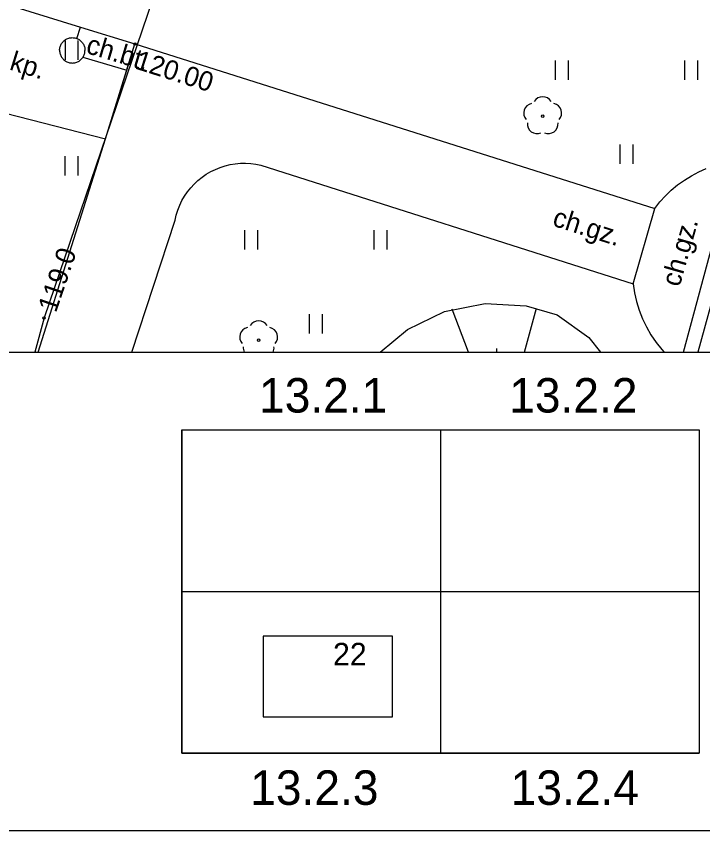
# Model space of a CAD drawing. Extents: x 6432121 to 6432331, y 5662538 to 5662686.
# Drawn here: x 6432202.58 to 6432229.11, y 5662537.55 to 5662569.04 of the extents above; entities that cross this region are included whole.
import ezdxf

# ---------------------------------------------------------------- set-up
doc = ezdxf.new("R2010")
doc.units = 0
for name, color, linetype in [('Warstwa 10', 7, 'Continuous'), ('Warstwa 11', 7, 'Continuous'), ('Warstwa 12', 7, 'Continuous'), ('Warstwa 14', 7, 'Continuous'), ('Warstwa 21', 7, 'Continuous'), ('Warstwa 25', 7, 'Continuous'), ('Warstwa 5', 7, 'Continuous'), ('Warstwa 63', 7, 'Continuous'), ('Warstwa 9', 7, 'Continuous')]:
    doc.layers.add(name, color=color, linetype=linetype)

msp = doc.modelspace()

# ---------------------------------------------------------------- linework, layer by layer
at = {"layer": 'Warstwa 10'}
for p, q in [((6432219.138, 5662557.621), (6432220.701, 5662557.93)), ((6432220.062, 5662556.053), (6432219.432, 5662557.711)), ((6432220.701, 5662557.93), (6432222.291, 5662557.843)), ((6432222.221, 5662556.053), (6432222.684, 5662557.758)), ((6432222.291, 5662557.843), (6432223.49, 5662557.5)), ((6432217.701, 5662556.933), (6432219.138, 5662557.621)), ((6432223.49, 5662557.5), (6432224.707, 5662556.621)), ((6432216.651, 5662556.053), (6432217.701, 5662556.933)), ((6432224.707, 5662556.621), (6432225.166, 5662556.053)), ((6432221.158, 5662556.053), (6432221.151, 5662556.197))]:
    msp.add_line(p, q, dxfattribs=at)
at = {"layer": 'Warstwa 11'}
for centre in [(6432222.929, 5662565.181), (6432211.95, 5662556.52)]:
    msp.add_circle(centre, 0.05, dxfattribs=at)
for centre, start, end in [((6432222.929, 5662565.556), 30.1471, 149.8529), ((6432222.572, 5662565.297), 102.1471, 221.8529), ((6432223.286, 5662565.297), 318.1471, 77.8529), ((6432222.709, 5662564.878), 174.1471, 293.8529), ((6432223.149, 5662564.878), 246.1471, 5.8529), ((6432211.95, 5662556.895), 30.1471, 149.8529), ((6432211.593, 5662556.636), 102.1471, 221.8529), ((6432212.307, 5662556.636), 318.1471, 77.8529), ((6432211.73, 5662556.217), 174.1471, 205.8431), ((6432212.17, 5662556.217), 334.1569, 5.8529)]:
    msp.add_arc(centre, 0.375, start, end, dxfattribs=at)
at = {"layer": 'Warstwa 12'}
for points in [[(6432127.185, 5662618.897), (6432135.629, 5662615.848), (6432142.79, 5662613.281), (6432154.997, 5662608.849), (6432160.46, 5662606.879), (6432165.736, 5662604.745), (6432167.852, 5662603.89), (6432175.869, 5662600.716), (6432188.607, 5662595.673), (6432197.141, 5662592.258), (6432208.285, 5662587.853), (6432217.328, 5662584.25), (6432226.269, 5662580.703), (6432229.116, 5662579.575), (6432234.631, 5662577.404), (6432234.076, 5662575.247), (6432232.817, 5662570.334), (6432230.472, 5662561.671), (6432228.926, 5662556.053)], [(6432228.367, 5662556.053), (6432231.658, 5662568.249), (6432233.96, 5662576.659), (6432221.597, 5662581.652), (6432210.31, 5662586.256), (6432196.752, 5662591.605), (6432184.96, 5662596.314), (6432169.081, 5662602.651), (6432160.264, 5662606.196), (6432148.936, 5662610.33), (6432147.827, 5662610.792), (6432135.842, 5662615.166), (6432127.959, 5662618.065)], [(6432211.625, 5662582.375), (6432211.84, 5662582.28), (6432211.83, 5662581.38), (6432203.66, 5662557.38), (6432203.3, 5662556.053)]]:
    msp.add_lwpolyline(points, dxfattribs=at)
at = {"layer": 'Warstwa 14'}
msp.add_circle((6432203.66, 5662557.38), 0.045, dxfattribs=at)
at = {"layer": 'Warstwa 21'}
for p, q in [((6432219.138, 5662557.621), (6432220.701, 5662557.93)), ((6432220.701, 5662557.93), (6432222.291, 5662557.843)), ((6432222.291, 5662557.843), (6432223.49, 5662557.5)), ((6432217.701, 5662556.933), (6432219.138, 5662557.621)), ((6432223.49, 5662557.5), (6432224.707, 5662556.621)), ((6432216.651, 5662556.053), (6432217.701, 5662556.933)), ((6432224.707, 5662556.621), (6432225.166, 5662556.053))]:
    msp.add_line(p, q, dxfattribs=at)
at = {"layer": 'Warstwa 25'}
msp.add_circle((6432207.17, 5662567.97), 0.045, dxfattribs=at)
at = {"layer": 'Warstwa 5'}
for p, q in [((6432198.6, 5662570.62), (6432205.062, 5662568.622)), ((6432205.062, 5662568.622), (6432207.17, 5662567.97)), ((6432204.355, 5662568.017), (6432204.376, 5662568.044)), ((6432204.376, 5662568.044), (6432204.4, 5662568.07)), ((6432204.4, 5662568.07), (6432204.426, 5662568.094)), ((6432204.426, 5662568.094), (6432204.453, 5662568.116)), ((6432204.453, 5662568.116), (6432204.482, 5662568.136)), ((6432204.481, 5662567.358), (6432204.481, 5662568.108)), ((6432204.482, 5662568.136), (6432204.512, 5662568.154)), ((6432204.512, 5662568.154), (6432204.543, 5662568.169)), ((6432204.543, 5662568.169), (6432204.576, 5662568.183)), ((6432204.576, 5662568.183), (6432204.609, 5662568.194)), ((6432204.609, 5662568.194), (6432204.643, 5662568.202)), ((6432204.643, 5662568.202), (6432204.677, 5662568.209)), ((6432204.677, 5662568.209), (6432204.712, 5662568.212)), ((6432204.712, 5662568.212), (6432204.747, 5662568.214)), ((6432204.747, 5662568.214), (6432204.782, 5662568.212)), ((6432204.782, 5662568.212), (6432204.817, 5662568.209)), ((6432204.817, 5662568.209), (6432204.851, 5662568.202)), ((6432204.851, 5662568.202), (6432204.885, 5662568.194)), ((6432204.885, 5662568.194), (6432204.918, 5662568.183)), ((6432204.918, 5662568.183), (6432204.951, 5662568.169)), ((6432204.951, 5662568.169), (6432204.982, 5662568.154)), ((6432204.981, 5662567.358), (6432204.981, 5662568.108)), ((6432204.982, 5662568.154), (6432205.012, 5662568.136)), ((6432205.012, 5662568.136), (6432205.041, 5662568.116)), ((6432205.041, 5662568.116), (6432205.068, 5662568.094)), ((6432205.068, 5662568.094), (6432205.094, 5662568.07)), ((6432205.094, 5662568.07), (6432205.118, 5662568.044)), ((6432205.118, 5662568.044), (6432205.139, 5662568.017)), ((6432204.257, 5662567.724), (6432204.258, 5662567.758)), ((6432204.257, 5662567.724), (6432204.258, 5662567.689)), ((6432204.258, 5662567.758), (6432204.262, 5662567.793)), ((6432204.262, 5662567.793), (6432204.268, 5662567.828)), ((6432204.268, 5662567.828), (6432204.276, 5662567.862)), ((6432204.276, 5662567.862), (6432204.288, 5662567.895)), ((6432204.288, 5662567.895), (6432204.301, 5662567.927)), ((6432204.301, 5662567.927), (6432204.317, 5662567.958)), ((6432204.317, 5662567.958), (6432204.335, 5662567.988)), ((6432204.335, 5662567.988), (6432204.355, 5662568.017)), ((6432205.139, 5662568.017), (6432205.159, 5662567.988)), ((6432205.159, 5662567.988), (6432205.177, 5662567.958)), ((6432205.177, 5662567.958), (6432205.193, 5662567.927)), ((6432205.193, 5662567.927), (6432205.206, 5662567.895)), ((6432205.206, 5662567.895), (6432205.218, 5662567.862)), ((6432205.218, 5662567.862), (6432205.226, 5662567.828)), ((6432205.226, 5662567.828), (6432205.232, 5662567.793)), ((6432205.232, 5662567.793), (6432205.236, 5662567.758)), ((6432205.236, 5662567.758), (6432205.238, 5662567.723)), ((6432205.236, 5662567.689), (6432205.238, 5662567.723)), ((6432207.17, 5662567.97), (6432227.26, 5662561.61)), ((6432204.258, 5662567.689), (6432204.262, 5662567.654)), ((6432204.262, 5662567.654), (6432204.268, 5662567.619)), ((6432204.268, 5662567.619), (6432204.276, 5662567.585)), ((6432204.276, 5662567.585), (6432204.288, 5662567.552)), ((6432204.288, 5662567.552), (6432204.301, 5662567.52)), ((6432204.301, 5662567.52), (6432204.317, 5662567.489)), ((6432204.317, 5662567.489), (6432204.335, 5662567.459)), ((6432204.335, 5662567.459), (6432204.355, 5662567.43)), ((6432204.355, 5662567.43), (6432204.376, 5662567.403)), ((6432205.118, 5662567.403), (6432205.139, 5662567.43)), ((6432205.139, 5662567.43), (6432205.159, 5662567.459)), ((6432205.159, 5662567.459), (6432205.177, 5662567.489)), ((6432205.177, 5662567.489), (6432205.193, 5662567.52)), ((6432205.193, 5662567.52), (6432205.206, 5662567.552)), ((6432205.206, 5662567.552), (6432205.218, 5662567.585)), ((6432205.218, 5662567.585), (6432205.226, 5662567.619)), ((6432205.226, 5662567.619), (6432205.232, 5662567.654)), ((6432205.232, 5662567.654), (6432205.236, 5662567.689)), ((6432204.376, 5662567.403), (6432204.4, 5662567.377)), ((6432204.4, 5662567.377), (6432204.426, 5662567.353)), ((6432204.426, 5662567.353), (6432204.453, 5662567.331)), ((6432204.453, 5662567.331), (6432204.482, 5662567.311)), ((6432204.482, 5662567.311), (6432204.512, 5662567.293)), ((6432204.512, 5662567.293), (6432204.543, 5662567.278)), ((6432204.543, 5662567.278), (6432204.576, 5662567.264)), ((6432204.576, 5662567.264), (6432204.609, 5662567.253)), ((6432204.609, 5662567.253), (6432204.643, 5662567.245)), ((6432204.643, 5662567.245), (6432204.677, 5662567.238)), ((6432204.677, 5662567.238), (6432204.712, 5662567.235)), ((6432204.712, 5662567.235), (6432204.747, 5662567.233)), ((6432204.747, 5662567.233), (6432204.782, 5662567.235)), ((6432204.782, 5662567.235), (6432204.817, 5662567.238)), ((6432204.817, 5662567.238), (6432204.851, 5662567.245)), ((6432204.851, 5662567.245), (6432204.885, 5662567.253)), ((6432204.885, 5662567.253), (6432204.918, 5662567.264)), ((6432204.918, 5662567.264), (6432204.951, 5662567.278)), ((6432204.951, 5662567.278), (6432204.982, 5662567.293)), ((6432204.982, 5662567.293), (6432205.012, 5662567.311)), ((6432205.012, 5662567.311), (6432205.041, 5662567.331)), ((6432205.041, 5662567.331), (6432205.068, 5662567.353)), ((6432205.068, 5662567.353), (6432205.094, 5662567.377)), ((6432205.094, 5662567.377), (6432205.118, 5662567.403)), ((6432223.423, 5662566.583), (6432223.423, 5662567.333)), ((6432223.923, 5662566.583), (6432223.923, 5662567.333)), ((6432228.423, 5662566.583), (6432228.423, 5662567.333)), ((6432228.923, 5662566.583), (6432228.923, 5662567.333)), ((6432202.17, 5662565.29), (6432206.03, 5662564.3)), ((6432203.432, 5662556.053), (6432206.03, 5662564.3)), ((6432225.923, 5662563.333), (6432225.923, 5662564.083)), ((6432226.423, 5662563.333), (6432226.423, 5662564.083)), ((6432204.475, 5662562.886), (6432204.475, 5662563.636)), ((6432204.975, 5662562.886), (6432204.975, 5662563.636)), ((6432210.848, 5662563.304), (6432211.046, 5662563.337)), ((6432211.046, 5662563.337), (6432211.245, 5662563.355)), ((6432211.245, 5662563.355), (6432211.445, 5662563.358)), ((6432211.445, 5662563.358), (6432211.645, 5662563.347)), ((6432211.645, 5662563.347), (6432211.844, 5662563.321)), ((6432211.844, 5662563.321), (6432212.04, 5662563.28)), ((6432209.926, 5662562.931), (6432210.098, 5662563.033)), ((6432210.098, 5662563.033), (6432210.278, 5662563.121)), ((6432210.278, 5662563.121), (6432210.463, 5662563.196)), ((6432210.463, 5662563.196), (6432210.654, 5662563.257)), ((6432210.654, 5662563.257), (6432210.848, 5662563.304)), ((6432212.04, 5662563.28), (6432226.43, 5662558.7)), ((6432228.675, 5662562.876), (6432228.958, 5662563.022)), ((6432228.958, 5662563.022), (6432229.251, 5662563.149)), ((6432209.459, 5662562.555), (6432209.605, 5662562.692)), ((6432209.605, 5662562.692), (6432209.761, 5662562.817)), ((6432209.761, 5662562.817), (6432209.926, 5662562.931)), ((6432228.145, 5662562.523), (6432228.404, 5662562.709)), ((6432228.404, 5662562.709), (6432228.675, 5662562.876)), ((6432209.199, 5662562.251), (6432209.323, 5662562.408)), ((6432209.323, 5662562.408), (6432209.459, 5662562.555)), ((6432227.9, 5662562.319), (6432228.145, 5662562.523)), ((6432208.986, 5662561.912), (6432209.086, 5662562.086)), ((6432209.086, 5662562.086), (6432209.199, 5662562.251)), ((6432227.456, 5662561.861), (6432227.67, 5662562.098)), ((6432227.67, 5662562.098), (6432227.9, 5662562.319)), ((6432208.899, 5662561.732), (6432208.986, 5662561.912)), ((6432227.26, 5662561.61), (6432227.456, 5662561.861)), ((6432208.765, 5662561.355), (6432208.825, 5662561.546)), ((6432208.825, 5662561.546), (6432208.899, 5662561.732)), ((6432207.044, 5662556.053), (6432208.72, 5662561.16)), ((6432208.72, 5662561.16), (6432208.765, 5662561.355)), ((6432211.416, 5662560.024), (6432211.416, 5662560.774)), ((6432211.916, 5662560.024), (6432211.916, 5662560.774)), ((6432216.416, 5662560.024), (6432216.416, 5662560.774)), ((6432216.916, 5662560.024), (6432216.916, 5662560.774)), ((6432226.43, 5662558.7), (6432226.479, 5662558.352)), ((6432226.479, 5662558.352), (6432226.555, 5662558.009)), ((6432226.555, 5662558.009), (6432226.657, 5662557.673)), ((6432226.657, 5662557.673), (6432226.784, 5662557.345)), ((6432213.916, 5662556.774), (6432213.916, 5662557.524)), ((6432214.416, 5662556.774), (6432214.416, 5662557.524)), ((6432226.784, 5662557.345), (6432226.935, 5662557.029)), ((6432226.935, 5662557.029), (6432227.111, 5662556.724)), ((6432227.111, 5662556.724), (6432227.309, 5662556.434)), ((6432227.309, 5662556.434), (6432227.529, 5662556.16)), ((6432227.529, 5662556.16), (6432227.629, 5662556.053))]:
    msp.add_line(p, q, dxfattribs=at)
at = {"layer": 'Warstwa 63'}
for p, q in [((6432208.976, 5662553.053), (6432228.976, 5662553.053)), ((6432208.976, 5662553.053), (6432208.976, 5662540.553)), ((6432218.976, 5662553.053), (6432218.976, 5662540.553)), ((6432228.976, 5662553.053), (6432228.976, 5662540.553)), ((6432208.976, 5662546.803), (6432228.976, 5662546.803)), ((6432208.976, 5662540.553), (6432228.976, 5662540.553))]:
    msp.add_line(p, q, dxfattribs=at)
for points in [[(6432120.976, 5662686.053), (6432330.976, 5662686.053), (6432330.976, 5662537.553), (6432120.976, 5662537.553)], [(6432125.976, 5662556.053), (6432325.976, 5662556.053), (6432325.976, 5662681.053), (6432125.976, 5662681.053)], [(6432208.976, 5662553.053), (6432228.976, 5662553.053), (6432228.976, 5662540.553), (6432208.976, 5662540.553)], [(6432212.126, 5662541.954), (6432217.126, 5662541.954), (6432217.126, 5662545.079), (6432212.126, 5662545.079)]]:
    msp.add_lwpolyline(points, close=True, dxfattribs=at)
at = {"layer": 'Warstwa 9'}
for p, q in [((6432198.6, 5662570.62), (6432205.062, 5662568.622)), ((6432204.918, 5662568.183), (6432205.062, 5662568.622)), ((6432204.918, 5662568.183), (6432205.062, 5662568.622)), ((6432205.062, 5662568.622), (6432207.17, 5662567.97)), ((6432204.355, 5662568.017), (6432204.376, 5662568.044)), ((6432204.376, 5662568.044), (6432204.4, 5662568.07)), ((6432204.4, 5662568.07), (6432204.426, 5662568.094)), ((6432204.426, 5662568.094), (6432204.453, 5662568.116)), ((6432204.453, 5662568.116), (6432204.482, 5662568.136)), ((6432204.482, 5662568.136), (6432204.512, 5662568.154)), ((6432204.512, 5662568.154), (6432204.543, 5662568.169)), ((6432204.543, 5662568.169), (6432204.576, 5662568.183)), ((6432204.576, 5662568.183), (6432204.609, 5662568.194)), ((6432204.609, 5662568.194), (6432204.643, 5662568.202)), ((6432204.643, 5662568.202), (6432204.677, 5662568.209)), ((6432204.677, 5662568.209), (6432204.712, 5662568.212)), ((6432204.712, 5662568.212), (6432204.747, 5662568.214)), ((6432204.747, 5662568.214), (6432204.782, 5662568.212)), ((6432204.782, 5662568.212), (6432204.817, 5662568.209)), ((6432204.817, 5662568.209), (6432204.851, 5662568.202)), ((6432204.851, 5662568.202), (6432204.885, 5662568.194)), ((6432204.885, 5662568.194), (6432204.918, 5662568.183)), ((6432204.918, 5662568.183), (6432204.951, 5662568.169)), ((6432204.951, 5662568.169), (6432204.982, 5662568.154)), ((6432204.982, 5662568.154), (6432205.012, 5662568.136)), ((6432205.012, 5662568.136), (6432205.041, 5662568.116)), ((6432205.041, 5662568.116), (6432205.068, 5662568.094)), ((6432205.068, 5662568.094), (6432205.094, 5662568.07)), ((6432205.094, 5662568.07), (6432205.118, 5662568.044)), ((6432205.118, 5662568.044), (6432205.139, 5662568.017)), ((6432204.257, 5662567.724), (6432204.258, 5662567.758)), ((6432204.257, 5662567.724), (6432204.258, 5662567.689)), ((6432204.258, 5662567.758), (6432204.262, 5662567.793)), ((6432204.262, 5662567.793), (6432204.268, 5662567.828)), ((6432204.268, 5662567.828), (6432204.276, 5662567.862)), ((6432204.276, 5662567.862), (6432204.288, 5662567.895)), ((6432204.288, 5662567.895), (6432204.301, 5662567.927)), ((6432204.301, 5662567.927), (6432204.317, 5662567.958)), ((6432204.317, 5662567.958), (6432204.335, 5662567.988)), ((6432204.335, 5662567.988), (6432204.355, 5662568.017)), ((6432205.139, 5662568.017), (6432205.159, 5662567.988)), ((6432205.159, 5662567.988), (6432205.177, 5662567.958)), ((6432205.177, 5662567.958), (6432205.193, 5662567.927)), ((6432205.193, 5662567.927), (6432205.206, 5662567.895)), ((6432205.206, 5662567.895), (6432205.218, 5662567.862)), ((6432205.218, 5662567.862), (6432205.226, 5662567.828)), ((6432205.226, 5662567.828), (6432205.232, 5662567.793)), ((6432205.232, 5662567.793), (6432205.236, 5662567.758)), ((6432205.236, 5662567.758), (6432205.238, 5662567.723)), ((6432205.236, 5662567.689), (6432205.238, 5662567.723)), ((6432206.03, 5662564.3), (6432207.17, 5662567.97)), ((6432206.854, 5662566.953), (6432207.17, 5662567.97)), ((6432207.17, 5662567.97), (6432227.26, 5662561.61)), ((6432204.258, 5662567.689), (6432204.262, 5662567.654)), ((6432204.262, 5662567.654), (6432204.268, 5662567.619)), ((6432204.268, 5662567.619), (6432204.276, 5662567.585)), ((6432204.276, 5662567.585), (6432204.288, 5662567.552)), ((6432204.288, 5662567.552), (6432204.301, 5662567.52)), ((6432204.301, 5662567.52), (6432204.317, 5662567.489)), ((6432204.317, 5662567.489), (6432204.335, 5662567.459)), ((6432204.335, 5662567.459), (6432204.355, 5662567.43)), ((6432204.355, 5662567.43), (6432204.376, 5662567.403)), ((6432205.118, 5662567.403), (6432205.139, 5662567.43)), ((6432205.139, 5662567.43), (6432205.159, 5662567.459)), ((6432205.159, 5662567.459), (6432205.177, 5662567.489)), ((6432205.159, 5662567.459), (6432206.854, 5662566.953)), ((6432205.159, 5662567.459), (6432206.854, 5662566.953)), ((6432205.177, 5662567.489), (6432205.193, 5662567.52)), ((6432205.193, 5662567.52), (6432205.206, 5662567.552)), ((6432205.206, 5662567.552), (6432205.218, 5662567.585)), ((6432205.218, 5662567.585), (6432205.226, 5662567.619)), ((6432205.226, 5662567.619), (6432205.232, 5662567.654)), ((6432205.232, 5662567.654), (6432205.236, 5662567.689)), ((6432204.376, 5662567.403), (6432204.4, 5662567.377)), ((6432204.4, 5662567.377), (6432204.426, 5662567.353)), ((6432204.426, 5662567.353), (6432204.453, 5662567.331)), ((6432204.453, 5662567.331), (6432204.482, 5662567.311)), ((6432204.482, 5662567.311), (6432204.512, 5662567.293)), ((6432204.512, 5662567.293), (6432204.543, 5662567.278)), ((6432204.543, 5662567.278), (6432204.576, 5662567.264)), ((6432204.576, 5662567.264), (6432204.609, 5662567.253)), ((6432204.609, 5662567.253), (6432204.643, 5662567.245)), ((6432204.643, 5662567.245), (6432204.677, 5662567.238)), ((6432204.677, 5662567.238), (6432204.712, 5662567.235)), ((6432204.712, 5662567.235), (6432204.747, 5662567.233)), ((6432204.747, 5662567.233), (6432204.782, 5662567.235)), ((6432204.782, 5662567.235), (6432204.817, 5662567.238)), ((6432204.817, 5662567.238), (6432204.851, 5662567.245)), ((6432204.851, 5662567.245), (6432204.885, 5662567.253)), ((6432204.885, 5662567.253), (6432204.918, 5662567.264)), ((6432204.918, 5662567.264), (6432204.951, 5662567.278)), ((6432204.951, 5662567.278), (6432204.982, 5662567.293)), ((6432204.982, 5662567.293), (6432205.012, 5662567.311)), ((6432205.012, 5662567.311), (6432205.041, 5662567.331)), ((6432205.041, 5662567.331), (6432205.068, 5662567.353)), ((6432205.068, 5662567.353), (6432205.094, 5662567.377)), ((6432205.094, 5662567.377), (6432205.118, 5662567.403)), ((6432206.03, 5662564.3), (6432206.854, 5662566.953)), ((6432202.17, 5662565.29), (6432206.03, 5662564.3)), ((6432203.432, 5662556.053), (6432206.03, 5662564.3)), ((6432210.848, 5662563.304), (6432211.046, 5662563.337)), ((6432211.046, 5662563.337), (6432211.245, 5662563.355)), ((6432211.245, 5662563.355), (6432211.445, 5662563.358)), ((6432211.445, 5662563.358), (6432211.645, 5662563.347)), ((6432211.645, 5662563.347), (6432211.844, 5662563.321)), ((6432211.844, 5662563.321), (6432212.04, 5662563.28)), ((6432209.926, 5662562.931), (6432210.098, 5662563.033)), ((6432210.098, 5662563.033), (6432210.278, 5662563.121)), ((6432210.278, 5662563.121), (6432210.463, 5662563.196)), ((6432210.463, 5662563.196), (6432210.654, 5662563.257)), ((6432210.654, 5662563.257), (6432210.848, 5662563.304)), ((6432212.04, 5662563.28), (6432226.43, 5662558.7)), ((6432228.675, 5662562.876), (6432228.958, 5662563.022)), ((6432228.958, 5662563.022), (6432229.251, 5662563.149)), ((6432209.459, 5662562.555), (6432209.605, 5662562.692)), ((6432209.605, 5662562.692), (6432209.761, 5662562.817)), ((6432209.761, 5662562.817), (6432209.926, 5662562.931)), ((6432228.145, 5662562.523), (6432228.404, 5662562.709)), ((6432228.404, 5662562.709), (6432228.675, 5662562.876)), ((6432209.199, 5662562.251), (6432209.323, 5662562.408)), ((6432209.323, 5662562.408), (6432209.459, 5662562.555)), ((6432227.9, 5662562.319), (6432228.145, 5662562.523)), ((6432208.986, 5662561.912), (6432209.086, 5662562.086)), ((6432209.086, 5662562.086), (6432209.199, 5662562.251)), ((6432227.456, 5662561.861), (6432227.67, 5662562.098)), ((6432227.67, 5662562.098), (6432227.9, 5662562.319)), ((6432208.899, 5662561.732), (6432208.986, 5662561.912)), ((6432227.26, 5662561.61), (6432227.456, 5662561.861)), ((6432208.765, 5662561.355), (6432208.825, 5662561.546)), ((6432208.825, 5662561.546), (6432208.899, 5662561.732)), ((6432226.43, 5662558.7), (6432227.26, 5662561.61)), ((6432226.43, 5662558.7), (6432227.26, 5662561.61)), ((6432207.044, 5662556.053), (6432208.72, 5662561.16)), ((6432208.72, 5662561.16), (6432208.765, 5662561.355)), ((6432226.43, 5662558.7), (6432226.479, 5662558.352)), ((6432226.479, 5662558.352), (6432226.555, 5662558.009)), ((6432226.555, 5662558.009), (6432226.657, 5662557.673)), ((6432226.657, 5662557.673), (6432226.784, 5662557.345)), ((6432226.784, 5662557.345), (6432226.935, 5662557.029)), ((6432226.935, 5662557.029), (6432227.111, 5662556.724)), ((6432227.111, 5662556.724), (6432227.309, 5662556.434)), ((6432227.309, 5662556.434), (6432227.529, 5662556.16)), ((6432227.529, 5662556.16), (6432227.629, 5662556.053))]:
    msp.add_line(p, q, dxfattribs=at)

# ---------------------------------------------------------------- texts
at = {"layer": 'Warstwa 14'}
msp.add_text('119.0', height=0.75, rotation=71.2015, dxfattribs=at).set_placement((6432204.114, 5662557.55))
at = {"layer": 'Warstwa 25'}
msp.add_text('120.00', height=0.75, rotation=342.434, dxfattribs=at).set_placement((6432207.13, 5662567.028))
at = {"layer": 'Warstwa 63'}
for s, height, p in [('13.2.1', 1.3333, (6432211.966, 5662553.72)), ('13.2.2', 1.3333, (6432221.635, 5662553.72)), ('22', 0.875, (6432214.824, 5662543.941)), ('13.2.3', 1.3333, (6432211.625, 5662538.553)), ('13.2.4', 1.3333, (6432221.693, 5662538.553))]:
    msp.add_text(s, height=height, dxfattribs=at).set_placement(p)
at = {"layer": 'Warstwa 9'}
for s, rotation, p in [('ch.bt.', 343.3908, (6432205.236, 5662567.63)), ('ch.kp.', 342.8178, (6432201.006, 5662567.384)), ('ch.gz.', 342.3423, (6432223.266, 5662560.957)), ('ch.gz.', 74.0834, (6432228.216, 5662558.547))]:
    msp.add_text(s, height=0.75, rotation=rotation, dxfattribs=at).set_placement(p)

doc.saveas('drawing.dxf')
